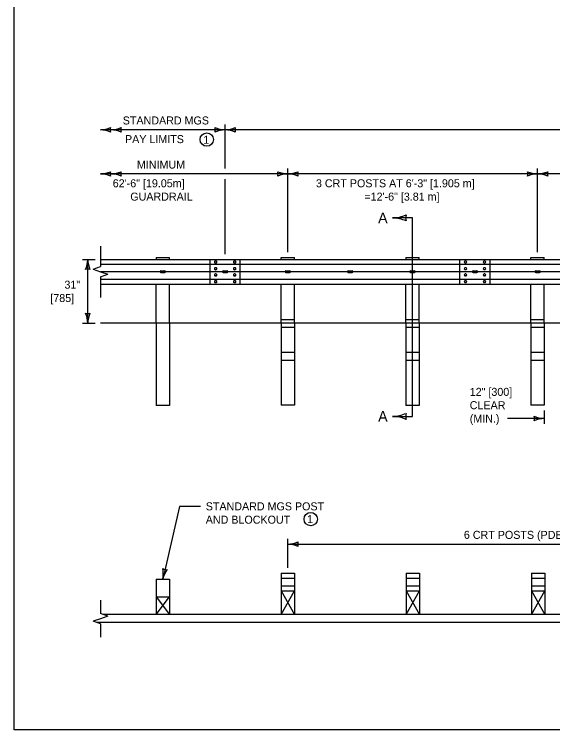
# Model space of a CAD drawing. Extents: x 49991.4 to 50021, y 49987.6 to 50011.4.
# Drawn here: x 49999.38 to 50003.42, y 49987.8 to 49993.16 of the extents above; entities that cross this region are included whole.
import ezdxf

# ---------------------------------------------------------------- set-up
doc = ezdxf.new("R2010")
doc.units = 0
for name, color, linetype in [('Level 1', 7, 'Continuous'), ('Level 2', 7, 'Continuous'), ('Level 3', 7, 'Continuous'), ('Level 4', 7, 'Continuous'), ('Level 5', 7, 'Continuous'), ('Level 6', 7, 'Continuous')]:
    doc.layers.add(name, color=color, linetype=linetype)

msp = doc.modelspace()

# ---------------------------------------------------------------- linework, layer by layer
at = {"layer": 'Level 1'}
for p, q in [((50000.0289, 49991.3233), (50010.4985, 49991.3233)), ((50000.0289, 49991.2873), (50010.4985, 49991.2873)), ((50000.4461, 49991.3365), (50000.4461, 49991.3233)), ((50000.4461, 49991.3365), (50000.5461, 49991.3365)), ((50000.5461, 49991.3233), (50000.5461, 49991.3365)), ((50000.8512, 49991.138), (50000.8512, 49991.3226)), ((50000.8954, 49991.311), (50000.8918, 49991.311)), ((50000.8954, 49991.2959), (50000.8918, 49991.2959)), ((50001.0376, 49991.311), (50001.034, 49991.311)), ((50001.0376, 49991.2959), (50001.034, 49991.2959)), ((50001.3842, 49991.3233), (50001.3842, 49991.3365)), ((50001.3842, 49991.3365), (50001.4841, 49991.3365)), ((50001.4841, 49991.3233), (50001.4841, 49991.3365)), ((50002.3186, 49991.3365), (50002.3186, 49991.3233)), ((50002.3186, 49991.3365), (50002.4186, 49991.3365)), ((50002.4186, 49991.3233), (50002.4186, 49991.3365)), ((50002.7236, 49991.138), (50002.7236, 49991.3226)), ((50002.7678, 49991.311), (50002.7642, 49991.311)), ((50002.7678, 49991.2959), (50002.7642, 49991.2959)), ((50002.9101, 49991.311), (50002.9065, 49991.311)), ((50002.9101, 49991.2959), (50002.9065, 49991.2959)), ((50003.2567, 49991.3233), (50003.2567, 49991.3366)), ((50003.2567, 49991.3366), (50003.3566, 49991.3366)), ((50003.3566, 49991.3233), (50003.3566, 49991.3366)), ((50000.4826, 49991.2373), (50000.5117, 49991.2373)), ((50000.8954, 49991.2611), (50000.8918, 49991.2611)), ((50000.8954, 49991.246), (50000.8918, 49991.246)), ((50000.9498, 49991.2373), (50000.979, 49991.2373)), ((50001.0376, 49991.2611), (50001.034, 49991.2611)), ((50001.0376, 49991.246), (50001.034, 49991.246)), ((50001.4196, 49991.2373), (50001.4487, 49991.2373)), ((50001.8868, 49991.2373), (50001.916, 49991.2373)), ((50002.354, 49991.2373), (50002.3832, 49991.2373)), ((50002.7678, 49991.2611), (50002.7642, 49991.2611)), ((50002.7678, 49991.246), (50002.7642, 49991.246)), ((50002.8223, 49991.2373), (50002.8514, 49991.2373)), ((50002.9101, 49991.2611), (50002.9065, 49991.2611)), ((50002.9101, 49991.246), (50002.9065, 49991.246)), ((50003.292, 49991.2373), (50003.3212, 49991.2373)), ((50000.4826, 49991.2248), (50000.5117, 49991.2248)), ((50000.8954, 49991.2146), (50000.8918, 49991.2146)), ((50000.8954, 49991.1995), (50000.8918, 49991.1995)), ((50000.9498, 49991.2248), (50000.979, 49991.2248)), ((50001.0376, 49991.2146), (50001.034, 49991.2146)), ((50001.0376, 49991.1995), (50001.034, 49991.1995)), ((50001.4196, 49991.2248), (50001.4487, 49991.2248)), ((50001.8868, 49991.2248), (50001.916, 49991.2248)), ((50002.354, 49991.2248), (50002.3832, 49991.2248)), ((50002.7678, 49991.2146), (50002.7642, 49991.2146)), ((50002.7678, 49991.1995), (50002.7642, 49991.1995)), ((50002.8223, 49991.2248), (50002.8514, 49991.2248)), ((50002.9101, 49991.2146), (50002.9065, 49991.2146)), ((50002.9101, 49991.1995), (50002.9065, 49991.1995)), ((50003.292, 49991.2248), (50003.3212, 49991.2248)), ((50000.0289, 49991.1748), (50010.4985, 49991.1748)), ((50000.0289, 49991.1388), (50010.4985, 49991.1388)), ((50000.4461, 49990.8443), (50000.4461, 49991.1388)), ((50000.5461, 49990.8443), (50000.5461, 49991.1388)), ((50000.8954, 49991.1647), (50000.8918, 49991.1647)), ((50000.8954, 49991.1496), (50000.8918, 49991.1496)), ((50001.0376, 49991.1647), (50001.034, 49991.1647)), ((50001.0376, 49991.1496), (50001.034, 49991.1496)), ((50001.3841, 49990.8443), (50001.3841, 49991.1388)), ((50001.4841, 49990.8443), (50001.4841, 49991.1388)), ((50002.3186, 49990.8443), (50002.3186, 49991.1388)), ((50002.4185, 49990.8443), (50002.4185, 49991.1388)), ((50002.7678, 49991.1647), (50002.7642, 49991.1647)), ((50002.7678, 49991.1496), (50002.7642, 49991.1496)), ((50002.9101, 49991.1647), (50002.9065, 49991.1647)), ((50002.9101, 49991.1496), (50002.9065, 49991.1496)), ((50003.2566, 49990.8443), (50003.2566, 49991.1388)), ((50003.3566, 49990.8443), (50003.3566, 49991.1388)), ((50010.4985, 49990.8443), (50000.0289, 49990.8443)), ((50001.3842, 49988.9722), (50001.3842, 49988.6612)), ((50001.3842, 49988.9722), (50001.4842, 49988.9722)), ((50001.4842, 49988.9722), (50001.4842, 49988.6612)), ((50002.3224, 49988.9722), (50002.3224, 49988.6612)), ((50002.3224, 49988.9722), (50002.4223, 49988.9722)), ((50002.4223, 49988.9722), (50002.4223, 49988.6612)), ((50003.2605, 49988.9722), (50003.2605, 49988.6612)), ((50003.2605, 49988.9722), (50003.3605, 49988.9722)), ((50003.3605, 49988.9722), (50003.3605, 49988.6612)), ((50000.4461, 49988.9278), (50000.5461, 49988.9278)), ((50000.4461, 49988.9278), (50000.4461, 49988.6612)), ((50000.5461, 49988.9278), (50000.5461, 49988.6612)), ((50001.3842, 49988.8389), (50001.4842, 49988.8389)), ((50001.3842, 49988.6612), (50001.4842, 49988.8389)), ((50001.3842, 49988.8389), (50001.4842, 49988.6612)), ((50002.3224, 49988.8389), (50002.4223, 49988.8389)), ((50002.3224, 49988.6612), (50002.4223, 49988.8389)), ((50002.3224, 49988.8389), (50002.4223, 49988.6612)), ((50003.2605, 49988.8389), (50003.3605, 49988.8389)), ((50003.2605, 49988.6612), (50003.3605, 49988.8389)), ((50003.2605, 49988.8389), (50003.3605, 49988.6612)), ((50000.4461, 49988.7945), (50000.5461, 49988.7945)), ((50000.4461, 49988.7945), (50000.5461, 49988.6612)), ((50000.4461, 49988.6612), (50000.5461, 49988.7945)), ((50003.6766, 49988.6612), (50000.0517, 49988.6612)), ((50003.6266, 49988.6012), (50000.0015, 49988.6012))]:
    msp.add_line(p, q, dxfattribs=at)
msp.add_lwpolyline([(49999.3835, 49998.9992), (50016.7501, 49998.9992), (50016.7501, 49987.7988), (49999.3835, 49987.7988)], close=True, dxfattribs=at)
for centre, start, end in [((50000.4826, 49991.231), 90, 180), ((50000.5117, 49991.231), 360, 90), ((50000.9498, 49991.231), 90, 180), ((50000.979, 49991.231), 360, 90), ((50001.4196, 49991.231), 90, 180), ((50001.4487, 49991.231), 360, 90), ((50001.8868, 49991.231), 90, 180), ((50001.916, 49991.231), 360, 90), ((50002.354, 49991.231), 90, 180), ((50002.3832, 49991.231), 360, 90), ((50002.8223, 49991.231), 90, 180), ((50002.8514, 49991.231), 360, 90), ((50003.292, 49991.231), 90, 180), ((50003.3212, 49991.231), 360, 90), ((50000.4826, 49991.231), 180, 270), ((50000.5117, 49991.231), 270, 0), ((50000.9498, 49991.231), 180, 270), ((50000.979, 49991.231), 270, 0), ((50001.4196, 49991.231), 180, 270), ((50001.4487, 49991.231), 270, 0), ((50001.8868, 49991.231), 180, 270), ((50001.916, 49991.231), 270, 0), ((50002.354, 49991.231), 180, 270), ((50002.3832, 49991.231), 270, 0), ((50002.8223, 49991.231), 180, 270), ((50002.8514, 49991.231), 270, 0), ((50003.292, 49991.231), 180, 270), ((50003.3212, 49991.231), 270, 0)]:
    msp.add_arc(centre, 0.00625, start, end, dxfattribs=at)
for centre, start_param, end_param in [((50000.8918, 49991.3035), 1.570796, 4.712389), ((50000.8954, 49991.3035), 4.712389, 7.853982), ((50001.034, 49991.3035), 1.570796, 4.712389), ((50001.0376, 49991.3035), 4.712389, 7.853982), ((50002.7642, 49991.3035), 1.570796, 4.712389), ((50002.7678, 49991.3035), 4.712389, 7.853982), ((50002.9065, 49991.3035), 1.570796, 4.712389), ((50002.9101, 49991.3035), 4.712389, 7.853982), ((50000.8918, 49991.2536), 1.570796, 4.712389), ((50000.8954, 49991.2536), 4.712389, 7.853982), ((50001.034, 49991.2536), 1.570796, 4.712389), ((50001.0376, 49991.2536), 4.712389, 7.853982), ((50002.7642, 49991.2536), 1.570796, 4.712389), ((50002.7678, 49991.2536), 4.712389, 7.853982), ((50002.9065, 49991.2536), 1.570796, 4.712389), ((50002.9101, 49991.2536), 4.712389, 7.853982), ((50000.8918, 49991.2071), 1.570796, 4.712389), ((50000.8954, 49991.2071), 4.712389, 7.853982), ((50001.034, 49991.2071), 1.570796, 4.712389), ((50001.0376, 49991.2071), 4.712389, 7.853982), ((50002.7642, 49991.2071), 1.570796, 4.712389), ((50002.7678, 49991.2071), 4.712389, 7.853982), ((50002.9065, 49991.2071), 1.570796, 4.712389), ((50002.9101, 49991.2071), 4.712389, 7.853982), ((50000.8918, 49991.1572), 1.570796, 4.712389), ((50000.8954, 49991.1572), 4.712389, 7.853982), ((50001.034, 49991.1572), 1.570796, 4.712389), ((50001.0376, 49991.1572), 4.712389, 7.853982), ((50002.7642, 49991.1572), 1.570796, 4.712389), ((50002.7678, 49991.1572), 4.712389, 7.853982), ((50002.9065, 49991.1572), 1.570796, 4.712389), ((50002.9101, 49991.1572), 4.712389, 7.853982)]:
    msp.add_ellipse(centre, major_axis=(0.00756, 0), ratio=0.998676, start_param=start_param, end_param=end_param, dxfattribs=at)
at = {"layer": 'Level 2'}
for centre in [(50000.8264, 49992.2217), (50001.6056, 49989.3772)]:
    msp.add_circle(centre, 0.05, dxfattribs=at)
at = {"layer": 'Level 3'}
for p, q in [((50000.9644, 49992.0038), (50000.9644, 49992.3346)), ((50008.4543, 49992.2946), (50000.0289, 49992.2946)), ((50001.4342, 49991.3766), (50001.4342, 49992.0038)), ((50003.3066, 49991.3766), (50003.3066, 49992.0038)), ((50001.4342, 49991.9638), (50000.0289, 49991.9638)), ((50003.3066, 49991.9638), (50001.4342, 49991.9638)), ((50005.1755, 49991.9638), (50003.3066, 49991.9638)), ((50000.9644, 49991.3633), (50000.9644, 49991.9238)), ((49999.894, 49991.3233), (49999.9889, 49991.3233)), ((49999.934, 49990.8443), (49999.934, 49991.3233)), ((49999.894, 49990.8443), (49999.9889, 49990.8443)), ((50003.3566, 49990.1902), (50003.3566, 49990.0907)), ((50003.3566, 49990.1307), (50003.0816, 49990.1307)), ((50000.6231, 49989.4727), (50000.4961, 49988.9278)), ((50000.7788, 49989.4727), (50000.6231, 49989.4727)), ((50001.4342, 49989.0122), (50001.4342, 49989.2289)), ((50001.4342, 49989.1889), (50007.0518, 49989.1889))]:
    msp.add_line(p, q, dxfattribs=at)
for centre, radius, start, end in [((50000.0174, 49992.5273), 0.233, 272.8273, 292.0772), ((50000.1571, 49992.2946), 0.0548, 162.1388, 197.8612), ((50000.0973, 49992.5273), 0.233, 272.8273, 292.0772), ((50000.237, 49992.2946), 0.0548, 162.1388, 197.8612), ((50000.9735, 49992.5167), 0.2223, 247.456, 267.6395), ((50000.8362, 49992.2946), 0.0548, 342.1388, 17.8612), ((50000.9529, 49992.5273), 0.233, 272.8273, 292.0772), ((50001.0926, 49992.2946), 0.0548, 162.1388, 197.8612), ((50000.0197, 49992.0724), 0.2223, 67.456, 87.6395), ((50000.0997, 49992.0724), 0.2223, 67.456, 87.6395), ((50000.9759, 49992.0618), 0.233, 92.8273, 112.0772), ((50000.9552, 49992.0724), 0.2223, 67.456, 87.6395), ((50000.0174, 49992.1965), 0.233, 272.8273, 292.0772), ((50000.0197, 49991.7416), 0.2223, 67.456, 87.6395), ((50000.1571, 49991.9638), 0.0548, 162.1388, 197.8612), ((50000.0973, 49992.1965), 0.233, 272.8273, 292.0772), ((50000.0997, 49991.7416), 0.2223, 67.456, 87.6395), ((50000.237, 49991.9638), 0.0548, 162.1388, 197.8612), ((50001.4433, 49992.1859), 0.2223, 247.456, 267.6395), ((50001.3059, 49991.9638), 0.0548, 342.1388, 17.8612), ((50001.4457, 49991.731), 0.233, 92.8273, 112.0772), ((50001.425, 49992.1859), 0.2223, 272.3605, 292.544), ((50001.4227, 49991.731), 0.233, 67.9228, 87.1727), ((50001.5624, 49991.9638), 0.0548, 162.1388, 197.8612), ((50003.3158, 49992.1859), 0.2223, 247.456, 267.6395), ((50003.1784, 49991.9638), 0.0548, 342.1388, 17.8612), ((50003.3181, 49991.731), 0.233, 92.8273, 112.0772), ((50003.2951, 49992.1965), 0.233, 272.8273, 292.0772), ((50003.2975, 49991.7416), 0.2223, 67.456, 87.6395), ((50003.4348, 49991.9638), 0.0548, 162.1388, 197.8612), ((50002.2073, 49991.9303), 0.2964, 272.3605, 292.544), ((50002.2041, 49991.3238), 0.3107, 67.9228, 87.1727), ((50002.3904, 49991.6341), 0.073, 162.1388, 197.8612), ((49999.7119, 49991.3325), 0.2223, 337.456, 357.6395), ((50000.1667, 49991.3348), 0.233, 182.8273, 202.0772), ((49999.934, 49991.1951), 0.0548, 72.1388, 107.8612), ((49999.934, 49990.9725), 0.0548, 252.1388, 287.8612), ((49999.7013, 49990.8328), 0.233, 2.8273, 22.0772), ((50000.1561, 49990.8352), 0.2223, 157.456, 177.6395), ((50002.2042, 49990.4573), 0.3107, 272.8273, 292.0772), ((50002.3905, 49990.147), 0.073, 162.1388, 197.8612), ((50002.2074, 49989.8509), 0.2964, 67.456, 87.6395), ((50003.3658, 49990.3529), 0.2223, 247.456, 267.6395), ((50003.2284, 49990.1307), 0.0548, 342.1388, 17.8612), ((50003.3681, 49989.898), 0.233, 92.8273, 112.0772), ((50001.4227, 49989.4216), 0.233, 272.8273, 292.0772), ((50001.5624, 49989.1889), 0.0548, 162.1388, 197.8612), ((50001.4251, 49988.9667), 0.2223, 67.456, 87.6395), ((50000.2777, 49988.9693), 0.2223, 349.2559, 9.4394), ((50000.7201, 49988.8639), 0.233, 144.8182, 164.0681), ((50000.5251, 49989.0527), 0.0548, 239.0342, 274.7566)]:
    msp.add_arc(centre, radius, start, end, dxfattribs=at)
at = {"layer": 'Level 4'}
for p, q in [((50001.0776, 49991.138), (50001.0776, 49991.3226)), ((50002.9501, 49991.138), (50002.9501, 49991.3226)), ((50001.3842, 49990.8734), (50001.4841, 49990.8734)), ((50002.3186, 49990.8734), (50002.4185, 49990.8734)), ((50003.2567, 49990.8735), (50003.3566, 49990.8735)), ((50000.4461, 49990.8443), (50000.4461, 49990.229)), ((50000.5461, 49990.8443), (50000.5461, 49990.229)), ((50001.3841, 49990.8443), (50001.3841, 49990.2302)), ((50001.3842, 49990.8151), (50001.4841, 49990.8151)), ((50001.4841, 49990.8443), (50001.4841, 49990.2302)), ((50002.3186, 49990.8443), (50002.3186, 49990.229)), ((50002.3186, 49990.8151), (50002.4185, 49990.8151)), ((50002.4185, 49990.8443), (50002.4185, 49990.229)), ((50003.2566, 49990.8443), (50003.2566, 49990.2302)), ((50003.2567, 49990.8152), (50003.3566, 49990.8152)), ((50003.3566, 49990.8443), (50003.3566, 49990.2302)), ((50001.3842, 49990.6273), (50001.4841, 49990.6273)), ((50002.3186, 49990.6273), (50002.4185, 49990.6273)), ((50003.2567, 49990.6274), (50003.3566, 49990.6274)), ((50001.3842, 49990.569), (50001.4841, 49990.569)), ((50002.3186, 49990.569), (50002.4185, 49990.569)), ((50003.2567, 49990.5691), (50003.3566, 49990.5691)), ((50000.5461, 49990.229), (50000.4461, 49990.229)), ((50001.4841, 49990.2302), (50001.3841, 49990.2302)), ((50002.4185, 49990.229), (50002.3186, 49990.229)), ((50003.3566, 49990.2302), (50003.2566, 49990.2302)), ((50001.3842, 49988.9347), (50001.4842, 49988.9347)), ((50002.3224, 49988.9347), (50002.4223, 49988.9347)), ((50003.2605, 49988.9347), (50003.3605, 49988.9347)), ((50001.3842, 49988.8764), (50001.4842, 49988.8764)), ((50002.3224, 49988.8764), (50002.4223, 49988.8764)), ((50003.2605, 49988.8764), (50003.3605, 49988.8764))]:
    msp.add_line(p, q, dxfattribs=at)
at = {"layer": 'Level 5'}
msp.add_line((50010.4985, 49991.231), (50000.0289, 49991.231), dxfattribs=at)
at = {"layer": 'Level 6'}
for p, q in [((50002.3685, 49991.6341), (50002.2195, 49991.6341)), ((50002.3686, 49990.1471), (50002.3685, 49991.6342)), ((50000.0289, 49991.4233), (50000.0289, 49991.2699)), ((49999.974, 49991.2505), (50000.0289, 49991.2699)), ((49999.974, 49991.2505), (50000.0289, 49991.231)), ((50000.0289, 49991.231), (50000.0837, 49991.2116)), ((50000.0289, 49991.1921), (50000.0837, 49991.2116)), ((50000.0289, 49991.1921), (50000.0289, 49991.0387)), ((50002.2196, 49990.147), (50002.3686, 49990.147)), ((50000.0289, 49988.7693), (50000.0289, 49988.6693)), ((50000.0838, 49988.6499), (50000.0289, 49988.6693)), ((50000.0289, 49988.6304), (49999.9741, 49988.611)), ((50000.0289, 49988.5915), (49999.9741, 49988.611)), ((50000.0838, 49988.6499), (50000.0289, 49988.6304)), ((50000.0289, 49988.5915), (50000.0289, 49988.4915))]:
    msp.add_line(p, q, dxfattribs=at)

# ---------------------------------------------------------------- texts
at = {"layer": 'Level 2'}
for s, height, p in [('STANDARD MGS', 0.06, (50000.1966, 49992.3346)), ('PAY LIMITS', 0.06, (50000.2135, 49992.1946)), ('1', 0.06, (50000.8007, 49992.1903)), ('MINIMUM', 0.06, (50000.3026, 49992.0038)), (' 62\'-6" [19.05m]', 0.06, (50000.0991, 49991.8638)), ('3 CRT POSTS AT 6\'-3" [1.905 m]', 0.06, (50001.6448, 49991.8638)), ('GUARDRAIL', 0.06, (50000.253, 49991.7638)), (' =12\'-6" [3.81 m] ', 0.06, (50001.9857, 49991.7638)), ('A', 0.0799, (50002.1109, 49991.5942)), ('31"', 0.06, (49999.7594, 49991.1038)), ('[785]', 0.06, (49999.6536, 49991.0038)), ('12" [300]', 0.06, (50002.7978, 49990.3007)), ('CLEAR', 0.06, (50002.7978, 49990.2007)), ('A', 0.0799, (50002.111, 49990.1071)), ('(MIN.)', 0.06, (50002.7978, 49990.1007)), ('STANDARD MGS POST', 0.06, (50000.8188, 49989.4427)), ('AND BLOCKOUT', 0.06, (50000.8188, 49989.3427)), ('1', 0.06, (50001.5786, 49989.3474)), ('6 CRT POSTS (PDE09*)  WITH ONE 12"[305] WOOD BLOCKOUT (PDB11*) EACH', 0.06, (50002.7539, 49989.2289))]:
    msp.add_text(s, height=height, dxfattribs=at).set_placement(p)

doc.saveas('drawing.dxf')
